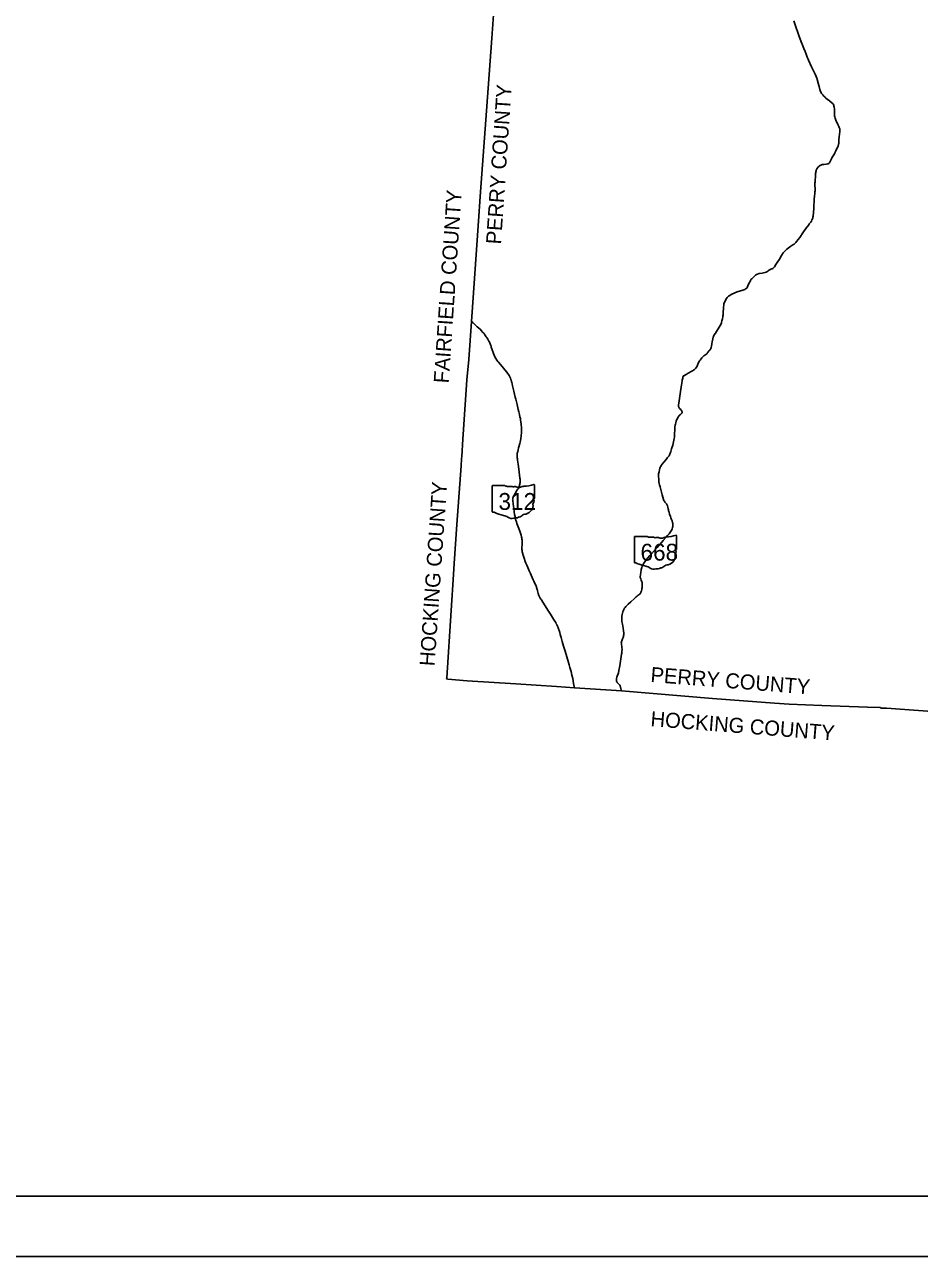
# Model space of a CAD drawing. Extents: x 1912787 to 2184787, y 543251 to 719251.
# Drawn here: x 1974302 to 2033774, y 543251 to 625080 of the extents above; entities that cross this region are included whole.
import ezdxf

# ---------------------------------------------------------------- set-up
doc = ezdxf.new("R2010")
doc.units = 0
for name, color, linetype in [('GM_X_County', 7, 'Continuous'), ('GM_X_County_Text', 7, 'Continuous'), ('GM_X_State_Location', 7, 'Continuous'), ('GM_X_State_Route', 7, 'Continuous'), ('GM_X_State_Shield', 7, 'Continuous'), ('SH_Border', 7, 'Continuous'), ('SH_Cut_Line', 7, 'Continuous')]:
    doc.layers.add(name, color=color, linetype=linetype)

msp = doc.modelspace()

# ---------------------------------------------------------------- linework, layer by layer
at = {"layer": 'GM_X_County'}
msp.add_lwpolyline([(2035533, 579371), (2031578, 579662), (2031215, 579678), (2031188, 579706), (2031156, 579716), (2030330, 579743), (2027283, 579852), (2025123, 579934), (2024154, 580009), (2020023, 580303), (2013972, 580821), (2010850, 581024), (2009648, 581116), (2006945, 581294), (2003722, 581480), (2002427, 581599), (2002351, 581613), (2002360, 581693), (2002660, 586158), (2002809, 588553), (2002855, 589279), (2003022, 591882), (2003270, 595169), (2003313, 595762), (2003346, 596263), (2003355, 596400), (2003432, 597550), (2003471, 598176), (2003691, 601489), (2003837, 602826), (2004013, 605355), (2004409, 611078), (2004446, 611711), (2004609, 613967), (2005008, 619347), (2005354, 624172), (2005566, 627003)], dxfattribs=at)
at = {"layer": 'GM_X_State_Route'}
msp.add_line((2006948, 600194), (2006918, 600325), dxfattribs=at)
for points in [[(2025952, 623837), (2025843, 624106), (2025753, 624367), (2025520, 625067), (2025429, 625340)], [(2018092, 601749), (2018113, 601758), (2018153, 601774), (2018194, 601789), (2018228, 601804), (2018281, 601837), (2018413, 601922), (2018646, 602052), (2018700, 602084), (2018761, 602125), (2018818, 602166), (2018867, 602208), (2018911, 602251), (2018959, 602316), (2018999, 602393), (2019023, 602448), (2019096, 602629), (2019129, 602695), (2019157, 602739), (2019201, 602797), (2019266, 602880), (2019321, 602949), (2019377, 603013), (2019438, 603073), (2019511, 603124), (2019584, 603168), (2019642, 603215), (2019671, 603247), (2019705, 603300), (2019731, 603345), (2019754, 603373), (2019779, 603403), (2019822, 603447), (2019858, 603484), (2019892, 603529), (2019915, 603573), (2019934, 603629), (2019953, 603724), (2019978, 603885), (2020003, 604014), (2020041, 604203), (2020073, 604322), (2020091, 604361), (2020142, 604461), (2020213, 604584), (2020348, 604799), (2020401, 604881), (2020472, 604991), (2020527, 605090), (2020568, 605168), (2020611, 605265), (2020630, 605322), (2020654, 605401), (2020684, 605530), (2020712, 605675), (2020720, 605730), (2020727, 605792), (2020732, 605875), (2020761, 606323), (2020769, 606418), (2020787, 606521), (2020808, 606588), (2020842, 606674), (2020910, 606813), (2020955, 606884), (2021008, 606959), (2021051, 607003), (2021077, 607031), (2021123, 607064), (2021173, 607096), (2021256, 607141), (2021343, 607190), (2021410, 607226), (2021460, 607251), (2021513, 607272), (2021667, 607319), (2021886, 607384), (2021970, 607411), (2022038, 607435), (2022098, 607460), (2022170, 607493), (2022221, 607518), (2022255, 607540), (2022296, 607578), (2022317, 607606), (2022374, 607718), (2022468, 607918), (2022519, 608021), (2022554, 608089), (2022580, 608133), (2022600, 608163), (2022631, 608196), (2022678, 608239), (2022774, 608323), (2022839, 608390), (2022884, 608432), (2022915, 608458), (2022941, 608476), (2022971, 608492), (2023020, 608512), (2023116, 608537), (2023326, 608578), (2023415, 608595), (2023504, 608612), (2023581, 608636), (2023643, 608663), (2023691, 608695), (2023715, 608715), (2023751, 608747), (2023790, 608772), (2023826, 608790), (2023865, 608806), (2023909, 608825), (2023971, 608849), (2023998, 608862), (2024023, 608874), (2024056, 608897), (2024084, 608920), (2024135, 608984), (2024240, 609150), (2024330, 609283), (2024468, 609507), (2024613, 609746), (2024726, 609912), (2024800, 609999), (2024870, 610073), (2024962, 610153), (2025057, 610232), (2025142, 610297), (2025226, 610359), (2025367, 610451), (2025445, 610502), (2025496, 610541), (2025526, 610568), (2025571, 610615), (2025613, 610668), (2025818, 610947), (2026026, 611250), (2026226, 611533), (2026421, 611789), (2026459, 611837), (2026509, 611902), (2026551, 611964), (2026594, 612033), (2026631, 612104), (2026661, 612170), (2026685, 612230), (2026700, 612296), (2026709, 612353), (2026755, 612861), (2026763, 612960), (2026765, 613113), (2026774, 613284), (2026788, 613489), (2026807, 613686), (2026822, 613857), (2026836, 613965), (2026841, 614038), (2026844, 614126), (2026842, 614246), (2026835, 614356), (2026832, 614432), (2026832, 614487), (2026834, 614568), (2026840, 614643), (2026849, 614758), (2026865, 614978), (2026871, 615105), (2026877, 615193), (2026882, 615255), (2026891, 615311), (2026904, 615373), (2026924, 615427), (2026939, 615461), (2026954, 615490), (2026974, 615525), (2027000, 615561), (2027026, 615594), (2027056, 615627), (2027090, 615656), (2027135, 615691), (2027183, 615721), (2027233, 615746), (2027275, 615762), (2027320, 615777), (2027417, 615795), (2027571, 615816), (2027664, 615828), (2027713, 615839), (2027753, 615856), (2027785, 615878), (2027806, 615901), (2027830, 615939), (2027933, 616168), (2027962, 616227), (2027999, 616294), (2028039, 616356), (2028090, 616438), (2028124, 616493), (2028163, 616565), (2028180, 616600), (2028225, 616690), (2028297, 616840), (2028350, 616959), (2028365, 616996), (2028385, 617041), (2028399, 617088), (2028409, 617143), (2028415, 617187), (2028424, 617321), (2028431, 617437), (2028447, 617636), (2028478, 617981), (2028483, 618026), (2028487, 618060), (2028486, 618105), (2028482, 618150), (2028470, 618197), (2028451, 618254), (2028429, 618302), (2028357, 618439), (2028304, 618546), (2028267, 618625), (2028242, 618674), (2028217, 618732), (2028191, 618798), (2028172, 618867), (2028156, 618944), (2028141, 619021), (2028135, 619084), (2028132, 619148), (2028132, 619207), (2028133, 619254), (2028138, 619344), (2028138, 619388), (2028128, 619469), (2028112, 619586), (2028097, 619674), (2028078, 619740), (2028053, 619798), (2028034, 619820), (2028014, 619842), (2027978, 619873), (2027791, 620022), (2027656, 620123), (2027565, 620195), (2027520, 620233), (2027480, 620273), (2027429, 620324), (2027348, 620420), (2027277, 620510), (2027236, 620571), (2027203, 620627), (2027174, 620698), (2027149, 620778), (2027103, 620963), (2027031, 621253), (2027020, 621308), (2027004, 621378), (2026988, 621444), (2026976, 621491), (2026961, 621529), (2026920, 621625), (2026847, 621785), (2026613, 622276), (2026412, 622710), (2026381, 622777), (2026325, 622915), (2026252, 623107), (2026176, 623303), (2026102, 623484), (2025978, 623773), (2025952, 623837)], [(2005753, 602703), (2005687, 602787), (2005619, 602889), (2005556, 603009), (2005462, 603240), (2005366, 603533), (2005321, 603663), (2005302, 603715), (2005269, 603801), (2005239, 603877), (2005214, 603935), (2005192, 603983), (2005165, 604042), (2005085, 604191), (2005053, 604248), (2005023, 604294), (2004989, 604347), (2004944, 604413), (2004895, 604479), (2004842, 604550), (2004789, 604614), (2004746, 604660), (2004664, 604747), (2004570, 604838), (2004392, 605002), (2004092, 605281), (2004014, 605352)], [(2006918, 600325), (2006818, 600739), (2006731, 601092), (2006702, 601217), (2006682, 601301), (2006661, 601381), (2006639, 601460), (2006621, 601513), (2006595, 601584), (2006573, 601632), (2006549, 601687), (2006523, 601736), (2006498, 601780), (2006470, 601826), (2006442, 601869), (2006414, 601910), (2006340, 602004), (2005924, 602497), (2005803, 602647), (2005753, 602703)], [(2017287, 592247), (2017259, 592320), (2017225, 592405), (2017168, 592568), (2017134, 592680), (2017105, 592788), (2017093, 592843), (2017075, 592914), (2017045, 593033), (2017024, 593104), (2017006, 593156), (2016988, 593195), (2016965, 593234), (2016942, 593267), (2016863, 593358), (2016822, 593415), (2016797, 593460), (2016771, 593526), (2016684, 593832), (2016542, 594378), (2016505, 594508), (2016485, 594589), (2016463, 594704), (2016453, 594834), (2016447, 594931), (2016445, 595018), (2016440, 595143), (2016442, 595227), (2016454, 595301), (2016469, 595369), (2016501, 595499), (2016532, 595610), (2016553, 595672), (2016580, 595732), (2016616, 595793), (2016688, 595886), (2016792, 596016), (2016942, 596198), (2017043, 596320), (2017097, 596386), (2017137, 596442), (2017164, 596491), (2017182, 596540), (2017245, 596711), (2017309, 596895), (2017378, 597136), (2017453, 597465), (2017475, 597587), (2017487, 597678), (2017498, 597815), (2017504, 597921), (2017511, 598146), (2017514, 598245), (2017526, 598361), (2017544, 598474), (2017555, 598534), (2017578, 598628), (2017604, 598734), (2017627, 598800), (2017655, 598857), (2017687, 598922), (2017727, 598985), (2017785, 599078), (2017817, 599111), (2017840, 599134), (2017906, 599190), (2017963, 599247), (2017983, 599276), (2018004, 599320), (2018009, 599342), (2018007, 599363), (2018001, 599383), (2017990, 599407), (2017967, 599440), (2017946, 599468), (2017913, 599502), (2017840, 599580), (2017805, 599619), (2017789, 599642), (2017775, 599670), (2017766, 599707), (2017763, 599754), (2017771, 599815), (2017791, 599935), (2017853, 600395), (2017877, 600554), (2017962, 601155), (2017977, 601244), (2018018, 601455), (2018044, 601587), (2018059, 601659), (2018067, 601693), (2018076, 601723), (2018083, 601738), (2018092, 601749)], [(2010851, 581021), (2010795, 581309), (2010729, 581634), (2010679, 581868), (2010623, 582096), (2010547, 582366), (2010491, 582558), (2010288, 583246), (2010208, 583517), (2010130, 583784), (2010037, 584103), (2009956, 584374), (2009904, 584557), (2009867, 584691), (2009829, 584833), (2009819, 584866), (2009803, 584913), (2009791, 584948), (2009774, 584998), (2009762, 585028), (2009745, 585071), (2009726, 585114), (2009707, 585153), (2009683, 585202), (2009667, 585232), (2009639, 585283), (2009599, 585350), (2009545, 585441), (2009494, 585526), (2009454, 585592), (2009381, 585702), (2009323, 585794), (2009247, 585912), (2009116, 586114), (2009073, 586185), (2008902, 586459), (2008749, 586704), (2008650, 586860), (2008620, 586909), (2008573, 586986), (2008549, 587027), (2008525, 587069), (2008506, 587107), (2008488, 587148), (2008465, 587202), (2008448, 587249), (2008435, 587295), (2008413, 587385), (2008393, 587469), (2008381, 587518), (2008371, 587561), (2008355, 587619), (2008335, 587685), (2008314, 587741), (2008301, 587776), (2008273, 587845), (2008222, 587959), (2008157, 588102), (2008111, 588202), (2008038, 588360), (2007969, 588511), (2007919, 588617), (2007845, 588783), (2007742, 589007), (2007674, 589164), (2007624, 589295), (2007581, 589410), (2007507, 589627), (2007438, 589832), (2007425, 589874), (2007410, 589928), (2007391, 589999), (2007381, 590050), (2007372, 590099), (2007366, 590146), (2007361, 590203), (2007359, 590264), (2007360, 590317), (2007369, 590532), (2007372, 590624), (2007372, 590710), (2007370, 590774), (2007365, 590832), (2007359, 590892), (2007346, 590970), (2007332, 591038), (2007320, 591088), (2007310, 591126), (2007298, 591170), (2007284, 591219), (2007232, 591364), (2007146, 591609), (2007067, 591820), (2007022, 591944), (2006989, 592045), (2006956, 592152), (2006938, 592213), (2006923, 592274), (2006896, 592400), (2006871, 592545), (2006848, 592714), (2006818, 592934), (2006774, 593234), (2006763, 593310), (2006749, 593408), (2006744, 593450), (2006741, 593488), (2006740, 593525), (2006741, 593558), (2006744, 593581), (2006748, 593605), (2006752, 593627), (2006758, 593650), (2006768, 593681), (2006775, 593702), (2006780, 593718), (2006793, 593744), (2006811, 593783), (2006837, 593827), (2006863, 593872), (2006900, 593929), (2007049, 594170), (2007072, 594204), (2007097, 594245), (2007125, 594292), (2007157, 594356), (2007180, 594412), (2007196, 594456), (2007205, 594494), (2007216, 594545), (2007226, 594601), (2007233, 594653), (2007237, 594705), (2007240, 594777), (2007241, 594832), (2007238, 594875), (2007227, 594953), (2007198, 595146), (2007165, 595355), (2007140, 595551), (2007099, 595878), (2007069, 596137), (2007058, 596225), (2007050, 596301), (2007045, 596363), (2007043, 596391), (2007042, 596425), (2007041, 596468), (2007042, 596515), (2007045, 596563), (2007050, 596604), (2007059, 596658), (2007076, 596730), (2007104, 596837), (2007139, 596974), (2007213, 597261), (2007235, 597352), (2007258, 597448), (2007278, 597564), (2007290, 597631), (2007301, 597713), (2007310, 597813), (2007317, 597931), (2007322, 598122), (2007323, 598230), (2007321, 598341), (2007314, 598462), (2007307, 598551), (2007291, 598679), (2007270, 598815), (2007254, 598903), (2007228, 599030), (2007192, 599189), (2007153, 599354), (2007117, 599504), (2007034, 599835), (2006948, 600194)], [(2016738, 590799), (2016943, 591035), (2017038, 591139), (2017134, 591249), (2017193, 591322), (2017242, 591389), (2017287, 591458), (2017321, 591520), (2017347, 591592), (2017369, 591666), (2017383, 591742), (2017390, 591805), (2017390, 591863), (2017382, 591929), (2017368, 592015), (2017334, 592125), (2017287, 592247)], [(2015249, 587343), (2015261, 587366), (2015295, 587458), (2015319, 587558), (2015330, 587624), (2015339, 587691), (2015346, 587766), (2015352, 587856), (2015354, 587908), (2015354, 587934), (2015352, 587972), (2015346, 588013), (2015333, 588065), (2015287, 588172), (2015250, 588256), (2015235, 588299), (2015225, 588354), (2015221, 588397), (2015233, 588528), (2015255, 588704), (2015275, 588833), (2015282, 588882), (2015322, 589024), (2015355, 589113), (2015389, 589182), (2015427, 589250), (2015461, 589300), (2015502, 589362), (2015588, 589485), (2015629, 589546), (2015667, 589599), (2015701, 589640), (2015867, 589819), (2015966, 589923), (2016137, 590112), (2016323, 590321)], [(2016323, 590321), (2016351, 590352), (2016658, 590707), (2016738, 590799)], [(2013974, 580818), (2013960, 580886), (2013935, 580977), (2013902, 581091), (2013893, 581117), (2013881, 581146), (2013855, 581192), (2013813, 581248), (2013692, 581374), (2013677, 581397), (2013667, 581422), (2013653, 581469), (2013641, 581534), (2013638, 581587), (2013644, 581651), (2013662, 581723), (2013682, 581787), (2013749, 581949), (2013769, 582022), (2013801, 582167), (2013858, 582489), (2013959, 583094), (2013984, 583257), (2013995, 583333), (2014005, 583428), (2014009, 583584), (2014006, 583685), (2013996, 583766), (2013974, 583897), (2013967, 583948), (2013963, 583996), (2013965, 584045), (2013971, 584082), (2013980, 584117), (2013993, 584151), (2014052, 584274), (2014086, 584355), (2014105, 584428), (2014117, 584489), (2014123, 584572), (2014123, 584650), (2014106, 584809), (2014075, 584979), (2014034, 585249), (2014006, 585430), (2014003, 585474), (2013993, 585569), (2013988, 585635), (2013989, 585696), (2013997, 585790), (2014014, 585885), (2014037, 585985), (2014055, 586059), (2014082, 586121), (2014104, 586171), (2014125, 586216), (2014146, 586258), (2014184, 586318), (2014220, 586367), (2014272, 586435), (2014336, 586500), (2014407, 586568), (2014600, 586744), (2014835, 586961), (2014956, 587069), (2015019, 587119), (2015090, 587176), (2015134, 587208), (2015168, 587237), (2015205, 587275), (2015237, 587320), (2015249, 587343)]]:
    msp.add_lwpolyline(points, dxfattribs=at)
at = {"layer": 'GM_X_State_Shield'}
for p, q in [((2005382, 594423), (2005382, 592722)), ((2006230, 594452), (2005410, 594452)), ((2008184, 593605), (2008184, 594494)), ((2008183, 593605), (2008184, 593605)), ((2014833, 591053), (2014833, 589351)), ((2015681, 591082), (2014861, 591082)), ((2017635, 590234), (2017635, 591124)), ((2017635, 590234), (2017635, 590234))]:
    msp.add_line(p, q, dxfattribs=at)
for centre, major_axis, start_param, end_param in [((2005414, 594427), (32.5, 0), 1.712693, 3.28349), ((2006425, 594650), (315, 0), 4.042523, 4.731795), ((2006530, 593497), (1130, 0), 1.404758, 1.657858), ((2006786, 594435), (90.8, 0), 3.836095, 5.185415), ((2006920, 594239), (189, 0), 0.950623, 2.079405), ((2007163, 594509), (227, 0), 4.081561, 5.145723), ((2007565, 593933), (598, 0), 1.699011, 2.107814), ((2007186, 596772), (2971, 0), 4.814394, 5.042369), ((2008153, 594498), (31.2, 0), 6.141152, 7.989035), ((2008295, 593232), (211, 0), 2.387724, 3.262537), ((2008176, 593539), (48.3, 0), 1.883978, 3.671073), ((2007869, 593427), (290, 0), 5.934695, 6.695948), ((2008150, 593601), (33.4, 0), 5.05454, 6.418171), ((2005414, 592718), (32.7, 0), 3.00124, 4.508301), ((2005419, 592892), (250, 0), 4.665946, 4.897461), ((2005470, 592624), (90.1, 0), 0.519207, 1.627899), ((2006608, 594152), (2146, 0), 4.195997, 4.488961), ((2005968, 591958), (671, 0), 0.823519, 1.323587), ((2007150, 592557), (240, 0), 4.937069, 5.64225), ((2007665, 592244), (407, 0), 1.647645, 2.488434), ((2007352, 593119), (743, 0), 5.101752, 6.440018), ((2006694, 592615), (426, 0), 4.026481, 4.996735), ((2006941, 592027), (350, 0), 1.495662, 1.94098), ((2006972, 592488), (227, 0), 4.691044, 5.507374), ((2007177, 592323), (63.9, 0), 1.147584, 2.315152), ((2014865, 591056), (32.5, 0), 1.712693, 3.28349), ((2015877, 591279), (315, 0), 4.042523, 4.731795), ((2015981, 590127), (1130, 0), 1.404758, 1.657858), ((2016238, 591065), (90.8, 0), 3.836095, 5.185415), ((2016371, 590868), (189, 0), 0.950623, 2.079405), ((2016615, 591138), (227, 0), 4.081561, 5.145723), ((2017016, 590562), (598, 0), 1.699011, 2.107814), ((2016637, 593401), (2971, 0), 4.814394, 5.042369), ((2017604, 591128), (31.2, 0), 6.141152, 7.989035), ((2017628, 590169), (48.3, 0), 1.883978, 3.671073), ((2017321, 590056), (290, 0), 5.934695, 6.695948), ((2017602, 590231), (33.4, 0), 5.05454, 6.418171), ((2014866, 589348), (32.7, 0), 3.00124, 4.508301), ((2014870, 589522), (250, 0), 4.665946, 4.897461), ((2014922, 589253), (90.1, 0), 0.519207, 1.627899), ((2016059, 590782), (2146, 0), 4.195997, 4.488961), ((2017117, 588874), (407, 0), 1.647645, 2.488434), ((2016803, 589749), (743, 0), 5.101752, 6.440018), ((2017747, 589862), (211, 0), 2.387724, 3.262537), ((2015420, 588587), (671, 0), 0.823519, 1.323587), ((2016146, 589245), (426, 0), 4.026481, 4.996735), ((2016392, 588657), (350, 0), 1.495662, 1.94098), ((2016423, 589117), (227, 0), 4.691044, 5.507374), ((2016628, 588953), (63.9, 0), 1.147584, 2.315152), ((2016601, 589187), (240, 0), 4.937069, 5.64225)]:
    msp.add_ellipse(centre, major_axis=major_axis, ratio=0.8, start_param=start_param, end_param=end_param, dxfattribs=at)
at = {"layer": 'SH_Border'}
msp.add_lwpolyline([(1924787, 715251), (2180787, 715251), (2180787, 547251), (1924787, 547251)], close=True, dxfattribs=at)
at = {"layer": 'SH_Cut_Line'}
msp.add_lwpolyline([(1912787, 543251), (2184787, 543251), (2184787, 719251), (1912787, 719251)], close=True, dxfattribs=at)

# ---------------------------------------------------------------- texts
at = {"layer": 'GM_X_County_Text'}
for s, rotation, p in [('PERRY COUNTY', 86.11607, (2005964, 610461)), ('FAIRFIELD COUNTY', 86.07844, (2002485, 601231)), ('HOCKING COUNTY', 86.07844, (2001551, 582438)), ('PERRY COUNTY', 355.51231, (2015878, 581414)), ('HOCKING COUNTY', 355.51231, (2015878, 578479))]:
    msp.add_text(s, height=1000, rotation=rotation, dxfattribs=at).set_placement(p)
at = {"layer": 'GM_X_State_Location'}
for s, p in [('312', (2006411, 593153)), ('668', (2015862, 589782))]:
    msp.add_text(s, height=1, rotation=0.00001, dxfattribs=at).set_placement(p)
for s, p in [('s', (2006764, 593225)), ('r', (2006764, 593225)), ('s', (2016216, 589855)), ('r', (2016215, 589855))]:
    msp.add_text(s, height=1, dxfattribs=at).set_placement(p)
at = {"layer": 'GM_X_State_Shield'}
for s, p in [('312', (2005798, 592842)), ('668', (2015238, 589471))]:
    msp.add_text(s, height=1120.7, dxfattribs=at).set_placement(p)

doc.saveas('drawing.dxf')
